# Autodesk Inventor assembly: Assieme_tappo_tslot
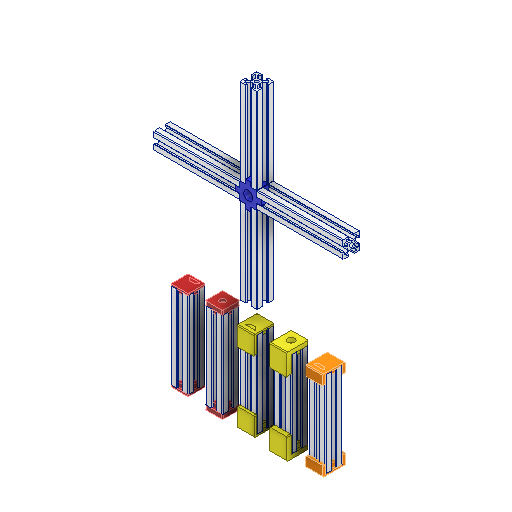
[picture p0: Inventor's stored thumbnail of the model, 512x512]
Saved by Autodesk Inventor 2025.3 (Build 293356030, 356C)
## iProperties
Created: 2026-02
Part Number: Assieme_tappo_tslot
Document SubType Name: Assembly
Designer: R5800u
Author: R5800u
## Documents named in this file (13)
- C:\Users\R5800u\Desktop\3d\antropomorfo_nema4\Assieme_tappo_tslot.iam
- C:\Users\R5800u\Desktop\3d\antropomorfo_nema4\tslot-20x20-3.ipt
- C:\Users\R5800u\Desktop\3d\antropomorfo_nema4\tappo_01.ipt
- C:\Users\R5800u\Desktop\3d\antropomorfo_nema4\tappo_02.ipt
- C:\Users\R5800u\Desktop\3d\antropomorfo_nema4\tappo_03.ipt
- C:\Users\R5800u\Desktop\3d\antropomorfo_nema4\tappo_04.ipt
- C:\Users\R5800u\Desktop\3d\antropomorfo_nema4\tappo_01_MIR1.ipt
- C:\Users\R5800u\Desktop\3d\antropomorfo_nema4\tappo_02_MIR1.ipt
- C:\Users\R5800u\Desktop\3d\antropomorfo_nema4\tappo_03_MIR1.ipt
- C:\Users\R5800u\Desktop\3d\antropomorfo_nema4\tappo_04_MIR1.ipt
- C:\Users\R5800u\Desktop\3d\antropomorfo_nema4\tappo_05.ipt
- C:\Users\R5800u\Desktop\3d\antropomorfo_nema4\tappo_05_MIR.ipt
- C:\Users\R5800u\Desktop\3d\antropomorfo_nema4\tappo6.ipt
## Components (20 placed, 12 different names)
1. tappo_01:1 — Allineato:1
2. tappo_02:1 — Coincidente:1, Allineato:2, Allineato:3
3. tappo_03:1 — Coincidente:2, Allineato:4, Allineato:5
4. tappo_04:1 — Coincidente:3, Allineato:6, Allineato:7
5. tappo_01_MIR1:1
6. tappo_02_MIR1:1
7. tappo_03_MIR1:1
8. tappo_04_MIR1:1
9. tappo_05:1 — Coincidente:4, Coincidente:5, Allineato:8
10. tappo_05_MIR:1
11. tappo6:1 — Coincidente:6, Allineato:10, Allineato:11
12. tslot-20x20-3:1 — Allineato:1
13. tslot-20x20-3:2 — Coincidente:1, Allineato:2, Allineato:3
14. tslot-20x20-3:3 — Coincidente:2, Allineato:4, Allineato:5, Allineato:12
15. tslot-20x20-3:4 — Coincidente:3, Allineato:6, Allineato:7
16. tslot-20x20-3:5 — Coincidente:4, Coincidente:5, Allineato:8, Allineato:9
17. tslot-20x20-3:6 — Allineato:9, Coincidente:6, Allineato:10, Allineato:11, Allineato:12
18. tslot-20x20-3:7
19. tslot-20x20-3:8
20. tslot-20x20-3:9
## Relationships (18: Flush 12, Mate 6)
- Allineato:1 [Flush]: tappo_01:1 ↔ tslot-20x20-3:1
- Coincidente:1 [Mate]: tappo_02:1 ↔ tslot-20x20-3:2
- Allineato:2 [Flush]: tappo_02:1 ↔ tslot-20x20-3:2
- Allineato:3 [Flush]: tappo_02:1 ↔ tslot-20x20-3:2
- Coincidente:2 [Mate]: tappo_03:1 ↔ tslot-20x20-3:3
- Allineato:4 [Flush]: tappo_03:1 ↔ tslot-20x20-3:3
- Allineato:5 [Flush]: tappo_03:1 ↔ tslot-20x20-3:3
- Coincidente:3 [Mate]: tappo_04:1 ↔ tslot-20x20-3:4
- Allineato:6 [Flush]: tappo_04:1 ↔ tslot-20x20-3:4
- Allineato:7 [Flush]: tappo_04:1 ↔ tslot-20x20-3:4
- Coincidente:4 [Mate]: tappo_05:1 ↔ tslot-20x20-3:5
- Coincidente:5 [Mate]: tappo_05:1 ↔ tslot-20x20-3:5
- Allineato:8 [Flush]: tappo_05:1 ↔ tslot-20x20-3:5
- Allineato:9 [Flush]: tslot-20x20-3:5 ↔ tslot-20x20-3:6
- Coincidente:6 [Mate]: tappo6:1 ↔ tslot-20x20-3:6
- Allineato:10 [Flush]: tappo6:1 ↔ tslot-20x20-3:6
- Allineato:11 [Flush]: tappo6:1 ↔ tslot-20x20-3:6
- Allineato:12 [Flush]: tslot-20x20-3:3 ↔ tslot-20x20-3:6
